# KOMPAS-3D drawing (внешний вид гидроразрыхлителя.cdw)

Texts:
  ВНЕШНИЙ ВИД ВСАСЫВАЮЩЕГО ТРУБОПРОВОДА И ГИДРОРАЗРЫХЛИТЕЛЯ РАСПОЛОЖЕНИЕ ДАТЧИКОВ
  Текст на чертеже
  Размерные надписи
  Шероховатость
  Линия-выноска #1
  Линия-выноска #2
  Линия-выноска #3
  Отклонения формы и база
  Заголовок таблицы
  Ячейка таблицы
  Стрелка вида
  Обозначение изменения
  Фигурная скобка
  Номер узла
  Марка координационной оси
  VRCB
  Выносная надпись
  Обозначение узла
  Марка/позиционное обозначение с линией-выноской
  Марка/позиционное обозначение на линии
  Марка/позиционное обозначение без линии-выноски
  поз
  обозначение
  наименнование
  кол
  масса
  материал
  примеч
  Датчик довления
  Датчик вакуума
  Датчик давления
  ВНЕШНИЙ ВИД ВСАСЫВАЮЩЕГО
  ТРУБОПРОВОДА И ГИДРОРАЗРЫХЛИТЕЛЯ
  РАСПОЛОЖЕНИЕ ДАТЧИКОВ
  Матюшко А.Н.
Dimensions and other numbers on the sheet: 7; 1; 2; 3; 0; 4; 5; 6; 8; 9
